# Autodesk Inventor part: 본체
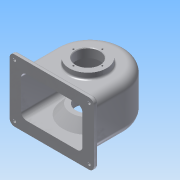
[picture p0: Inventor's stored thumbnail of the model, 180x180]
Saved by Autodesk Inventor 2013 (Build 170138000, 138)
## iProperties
Created: 2016-01
Part Number: 본체
Material: 알루미늄 6061
Document SubType Name: Modeling
Designer: mrc
Density: 2.71 g/cm^3
Mass: 812.694 g
Surface Area: 1004.25 cm^2
Volume: 299.887 cm^3
Author: mrc
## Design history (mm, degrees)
sketch "스케치3"
  geometry: L1 (-57, 0)-(-57, -64); L2 (57, 0)-(57, -64); L3 (-57, -64)-(57, -64); A1 r 57 centre (0, 0) between (57, 0) and (-57, 0); 1 further point
  constraints: 6 end point, 2 point on circle, 2 tangent, 1 centre point, 1 coincident, 1 parallel, 1 vertical
  dimensions: "d18" = 114 diameter of A1; "d19" = 64 distance of L1.start L1.end; "d20" = 64 distance of L2.start L2.end
extrude "돌출1" new body sketch "스케치3" distance "d21" = 77; taper "d22" = 0 deg
node "작업 평면1"
sketch "스케치5"
  geometry: L1 (-51, 0)-(-51, -64); L2 (51, 0)-(51, -64); L3 (57, -64)-(-57, -64) reference; L4 (-51, -64)-(51, -64); A1 r 51 centre (0, 0) between (51, 0) and (-51, 0); 1 further point
  constraints: 6 end point, 2 point on circle, 2 point on line, 2 tangent, 1 centre point, 1 coincident, 1 collinear, 1 parallel, 1 vertical
  dimensions: "d26" = 102 diameter of A1
extrude "돌출2" cut sketch "스케치5" distance "d27" = 67; taper "d28" = 0 deg
sketch "스케치6"
  geometry: C1 r 20 at (0, -4); A1 r 57 centre (0, 0) between (57, 0) and (-57, 0) reference
  constraints: 1 centre point, 1 vertical alignment
  dimensions: "d29" = 40 diameter of C1; "d30" = 4 distance of A1.centre C1.centre
extrude "돌출3" cut sketch "스케치6" distance "d31" = 126.75; taper "d32" = 0 deg
sketch "스케치7"
  geometry: C1 r 20 at (0, -4) reference; C2 r 31 at (0, -4); C3 r 20 at (0, -4)
  constraints: 2 centre point, 2 coincident
  dimensions: "d33" = 62 diameter of C2; "d34" = 40 diameter of C3
extrude "돌출4" join sketch "스케치7" distance "d35" = 10; taper "d36" = 0 deg
sketch "스케치8"
  geometry: C1 r 20 at (0, -4) reference; C2 r 28 at (0, -4); C3 r 20 at (0, -4)
  constraints: 2 centre point, 2 coincident
  dimensions: "d37" = 56 diameter of C2; "d38" = 40 diameter of C3
extrude "돌출5" join sketch "스케치8" distance "d39" = 16; taper "d40" = 0 deg
feature "면 기울기1" dims angle "d42" = 40 deg
sketch "스케치10"
  geometry: L1 (37.426, 5)-(24, 21) reference; L2 (-4, -2.299)-(-4, 40.983); L3 (30.899, 5)-(35.094, 0); L4 (30.899, 5)-(16, 5); L5 (24, 21)-(-32, 21) reference; L6 (0, 0)-(57, 0) reference; L7 (16, 5)-(16, 0); L8 (35.094, 0)-(16, 0)
  constraints: 10 end point, 2 perpendicular, 2 point on line, 1 collinear, 1 parallel
  dimensions: "d44" = 5 distance between parallel lines of L1 L3; "d45" = 16 distance between parallel lines of L4 L5; "d46" = 40 diameter of L7 L2
revolve "회전2" sketch "스케치10" stored, may be unused: angle "d47" = 90 deg
sketch "스케치11"
  geometry: L1 (108, 72)-(108, 5) reference; L2 (114, 0)-(0, 0) reference; L3 (114, 0)-(114, 77) reference; L4 (0, 77)-(114, 77) reference; L5 (-13, -13.5)-(127, -13.5); L6 (127, -13.5)-(127, 90.5); L7 (127, 90.5)-(-13, 90.5); L8 (-13, 90.5)-(-13, -13.5); L9 (0, 0)-(114, 0); L10 (114, 0)-(114, 77); L11 (114, 77)-(0, 77); L12 (0, 77)-(0, 0); 5 further points
  constraints: 16 end point, 4 midpoint, 4 parallel, 2 horizontal, 2 perpendicular, 1 horizontal alignment, 1 vertical alignment
  dimensions: "d48" = 140 distance of L6.end L7.end; "d50" = 104 distance of L5.end L6.end
extrude "돌출6" join sketch "스케치11" distance "d51" = 7; taper "d52" = 0 deg
node "작업 평면2"
sketch "스케치12"
  geometry: L1 (57, 77)-(-57, 77) reference; L2 (-57, 0)-(57, 0) reference; L3 (57, 0)-(57, 77) reference; C1 r 6 at (0, 38.5); 2 further points
  constraints: 1 centre point, 1 midpoint, 1 vertical alignment
  dimensions: "d54" = 12 diameter of C1; "d55" = 38.5 distance from line of L1 C1.centre
extrude "돌출7" join sketch "스케치12" stored distance "d56" = 7; taper "d57" = 0 deg
extrude "돌출8" join sketch "스케치12" distance "d58" = 6; taper "d59" = 0 deg
sketch "스케치13"
  geometry: C1 r 34.899 at (0, 0) reference; 2 further points
  constraints: 1 vertical alignment
  dimensions: "d60" = 28 distance of C1.centre point (0, 28)
hole "구멍1" sketch "스케치13" at (0, 28) diameter "d61" = 2.459; stored, may be unused: countersink angle "d65" = 90 deg, drill point angle "d67" = 118 deg; dims "d62" = 7, "d63" = 4, "d64" = 2, "d66" = 9
sketch "스케치14"
  geometry: C1 r 20 at (0, 0) reference; 2 further points
  constraints: 1 vertical alignment
  dimensions: "d71" = 24 distance of C1.centre point (0, 24)
hole "구멍2" sketch "스케치14" at (0, 24) diameter "d72" = 2.459; stored, may be unused: countersink angle "d76" = 90 deg, drill point angle "d78" = 118 deg; dims "d73" = 6, "d74" = 4, "d75" = 2, "d77" = 8
hole "구멍3" diameter "d84" = 4.459; stored, may be unused: countersink angle "d88" = 90 deg, drill point angle "d90" = 118 deg; dims "d82" = 10, "d83" = 10, "d85" = 30, "d86" = 4, "d87" = 2, "d89" = 53.25
sketch "스케치15"
  geometry: L1 (0, -57)-(0, 0) reference; L2 (90.5, -64)-(-13.5, -64) reference; 1 further point
  constraints: 1 other
  dimensions: "d91" = 38.5 distance from line of L1 point (38.5, -34); "d92" = 30 distance from line of point (38.5, -34) L2
fillet "모깎기1" dims "d93" = 8
hole "구멍4" diameter "d96" = 5; stored, may be unused: countersink angle "d100" = 90 deg, drill point angle "d102" = 0 deg; dims "d94" = 10, "d95" = 10, "d97" = 30, "d98" = 4, "d99" = 2, "d101" = 53.25
hole "구멍5" diameter "d105" = 5; stored, may be unused: countersink angle "d109" = 90 deg, drill point angle "d111" = 0 deg; dims "d103" = 10, "d104" = 10, "d106" = 30, "d107" = 4, "d108" = 2, "d110" = 53.25
hole "구멍6" diameter "d114" = 5; stored, may be unused: countersink angle "d118" = 90 deg, drill point angle "d120" = 0 deg; dims "d112" = 10, "d113" = 10, "d115" = 30, "d116" = 4, "d117" = 2, "d119" = 53.25
hole "구멍7" diameter "d123" = 5; stored, may be unused: countersink angle "d127" = 90 deg, drill point angle "d129" = 0 deg; dims "d121" = 10, "d122" = 10, "d124" = 30, "d125" = 4, "d126" = 2, "d128" = 53.25
fillet "모깎기2" dims "d130" = 3
feature "엠보싱1" dims "d18" = 114, "d19" = 64, "d20" = 64, "d131" = 0.5, "d132" = 0
fillet "모깎기3" dims "d133" = 9
fillet "모깎기5" dims "d135" = 14
fillet "모깎기6" dims "d136" = 1
fillet "모깎기7" dims "d137" = 3
chamfer "모따기1" distance "d138" = 1; stored, may be unused: second distance "d139" = 2, angle "d140" = 45 deg
chamfer "모따기2" distance "d141" = 1; stored, may be unused: second distance "d142" = 2, angle "d143" = 45 deg
fillet "모깎기8" dims "d144" = 3
fillet "모깎기9" dims "d145" = 3
fillet "모깎기10" dims "d146" = 3
node "솔리드2"
pattern_circular "원형 패턴1" dims angle "d69" = 360 deg
pattern_circular "원형 패턴2" dims angle "d80" = 360 deg
other parameters: "d25" = -5, "d53" = 57
